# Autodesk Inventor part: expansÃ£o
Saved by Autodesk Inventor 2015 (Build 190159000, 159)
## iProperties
Created: 2015-06
Part Number: expansÃ£o
Material: Generic
Document SubType Name: Modeling
Designer: Franzi-CAD
Density: 1 g/cm^3
Appearance: 166,83,0
Translation Standard: IGES 5.3
FileName: 1 Sistema de RefrigeraÃ§Ã£o Industrial - 3D v3
PreProcessor: AutoCAD 2015 - English
PostProcessor: Build: 160, Release: 2012 RTM - Date: Tue 03/01/2011
Sent Units: millimeter
Uncertainty: 0.01
Author: Franzi-CAD
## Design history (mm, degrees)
node "expansÃ£o1"
node "1 Sistema de Refrigeração Industrial - 3D v3"
node "Base1"
feature "Composite1"
body "Srf1"
